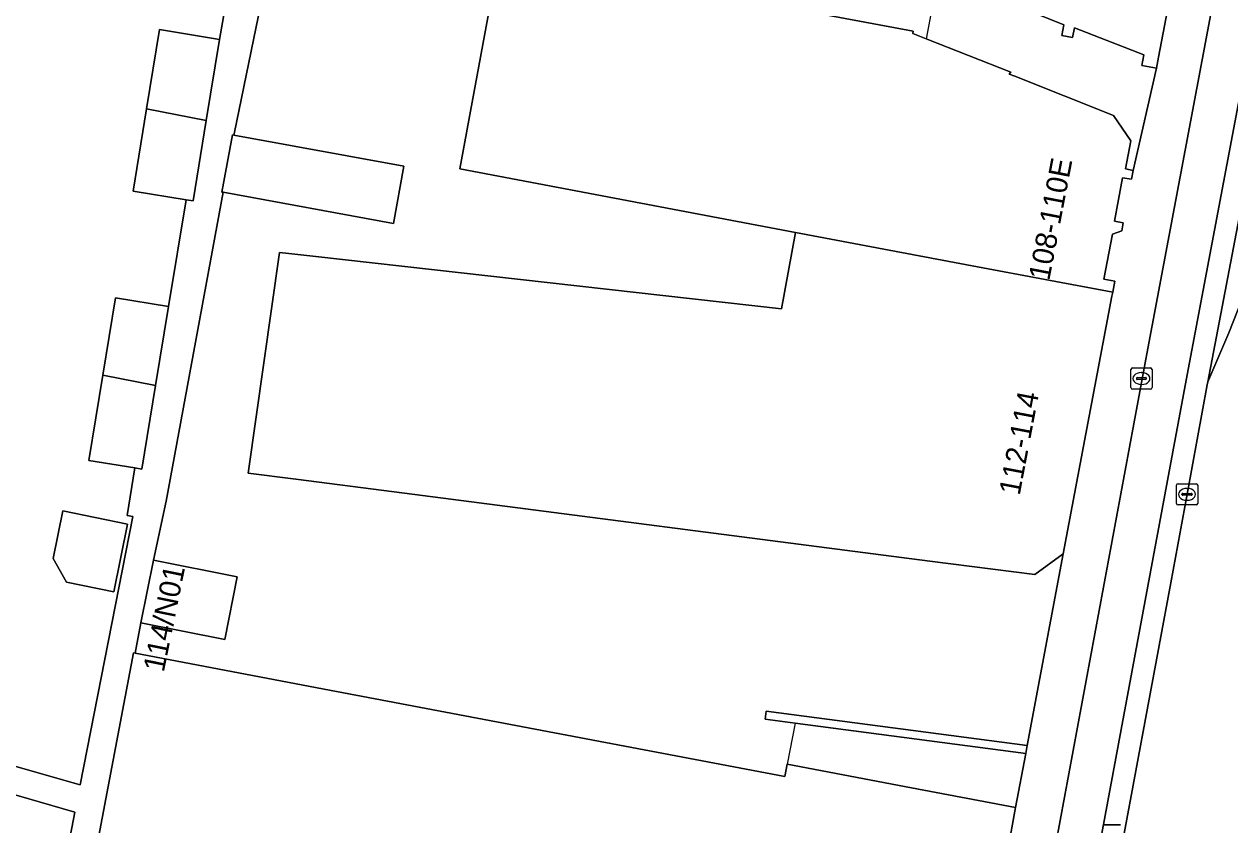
# Model space of a CAD drawing. Extents: x 161402 to 161933, y 381647 to 382315.
# Drawn here: x 161804.7 to 161861.6, y 381758.6 to 381796.3 of the extents above; entities that cross this region are included whole.
import ezdxf

# ---------------------------------------------------------------- set-up
doc = ezdxf.new("R2010")
doc.units = 0
for name, color, linetype in [('IMGEO_Berm_open', 7, 'Continuous'), ('IMGEO_Brandkraan', 7, 'Continuous'), ('IMGEO_Erf', 7, 'Continuous'), ('IMGEO_Fietspad_gesloten', 7, 'Continuous'), ('IMGEO_Kolk', 7, 'Continuous'), ('IMGEO_Pand', 7, 'Continuous'), ('IMGEO_Pand_nummerreeks', 7, 'Continuous'), ('IMGEO_Pand_overbouw', 7, 'Continuous'), ('IMGEO_Parkeervlak_open', 7, 'Continuous'), ('IMGEO_Rijbaan_lokaal_gesloten', 7, 'Continuous'), ('IMGEO_Voetpad_open', 7, 'Continuous'), ('IMGEO_Wegwijzer', 7, 'Continuous')]:
    doc.layers.add(name, color=color, linetype=linetype)

msp = doc.modelspace()

# ---------------------------------------------------------------- linework, layer by layer
at = {"layer": 'IMGEO_Berm_open'}
msp.add_lwpolyline([(161855.069, 381750), (161856.164, 381755.911), (161857.682, 381764.091), (161858.781, 381770.01), (161859.554, 381774.178), (161860.503, 381779.34), (161860.529, 381779.475), (161865.316, 381804.498), (161864.254, 381804.698), (161859.509, 381779.56), (161854.016, 381750), (161850.643, 381731.85), (161849.541, 381725.922), (161844.249, 381697.445)], dxfattribs=at)
at = {"layer": 'IMGEO_Brandkraan'}
for p, q in [((161856.902, 381779.209), (161856.902, 381780.061)), ((161856.977, 381780.135), (161857.829, 381780.135)), ((161857.903, 381780.061), (161857.903, 381779.209)), ((161857.161, 381779.629), (161857.161, 381779.641)), ((161857.599, 381779.592), (161857.201, 381779.592)), ((161857.204, 381779.678), (161857.602, 381779.678)), ((161857.39, 381779.915), (161857.415, 381779.915)), ((161857.645, 381779.641), (161857.645, 381779.629)), ((161857.829, 381779.135), (161856.977, 381779.135)), ((161857.413, 381779.355), (161857.388, 381779.355))]:
    msp.add_line(p, q, dxfattribs=at)
for points in [[(161856.902, 381779.209), (161856.902, 381780.061)], [(161856.977, 381780.135), (161857.829, 381780.135)], [(161857.903, 381780.061), (161857.903, 381779.209)], [(161857.829, 381779.135), (161856.977, 381779.135)]]:
    msp.add_lwpolyline(points, dxfattribs=at)
for centre, radius, start, end in [((161856.979, 381780.059), 0.0765, 91.552, 178.448), ((161856.979, 381780.059), 0.0765, 91.552, 178.448), ((161857.827, 381780.059), 0.0765, 1.552, 88.448), ((161857.827, 381780.059), 0.0765, 1.552, 88.448), ((161857.201, 381779.638), 0.0403, 85.8775, 175.7526), ((161857.198, 381779.628), 0.0366, 178.938, 274.7102), ((161857.602, 381779.635), 0.043, 264.8664, 352.4533), ((161857.606, 381779.64), 0.0386, 1.7309, 96.639), ((161856.979, 381779.211), 0.0765, 181.552, 268.448), ((161856.979, 381779.211), 0.0765, 181.552, 268.448), ((161857.827, 381779.211), 0.0765, 271.552, 358.448), ((161857.827, 381779.211), 0.0765, 271.552, 358.448)]:
    msp.add_arc(centre, radius, start, end, dxfattribs=at)
for centre, major_axis, ratio, start_param, end_param in [((161857.389, 381779.635), (-0.387, 0.002), 0.722429, 4.712389, 7.853982), ((161857.414, 381779.635), (-0.39, 0.002), 0.717154, 1.570796, 4.712389)]:
    msp.add_ellipse(centre, major_axis=major_axis, ratio=ratio, start_param=start_param, end_param=end_param, dxfattribs=at)
at = {"layer": 'IMGEO_Erf'}
for points in [[(161820.446, 381819.524), (161814.613, 381791.164), (161814.602, 381791.103), (161822.621, 381789.643), (161822.13, 381786.95), (161814.104, 381788.412), (161811.409, 381773.853), (161810.816, 381771.077), (161814.765, 381770.281), (161814.17, 381767.332), (161810.222, 381768.128), (161809.949, 381766.688), (161819.44, 381764.889), (161840.589, 381760.879), (161840.698, 381761.458), (161846.555, 381760.347), (161851.467, 381759.416), (161851.943, 381761.958), (161841.065, 381763.395), (161839.66, 381763.58), (161839.71, 381763.956), (161852.013, 381762.331), (161853.707, 381771.374), (161852.381, 381770.396), (161847.423, 381771.033), (161822.163, 381774.29), (161817.528, 381774.888), (161815.284, 381775.177), (161816.76, 381785.582), (161817.2, 381785.532), (161818.468, 381785.39), (161840.426, 381782.925), (161841.091, 381786.52), (161825.253, 381789.517), (161827.976, 381804.229)], [(161794.436, 381764.163), (161807.363, 381760.485), (161809.842, 381773.13), (161809.566, 381773.183), (161809.933, 381775.423), (161807.766, 381775.778), (161808.424, 381779.8), (161809.02, 381783.443), (161811.524, 381783.033), (161812.348, 381788.06), (161809.85, 381788.469), (161810.485, 381792.348), (161811.097, 381796.082), (161813.929, 381795.618), (161814.791, 381800.53)], [(161840.218, 381797.195), (161846.644, 381796.006), (161846.624, 381795.895), (161847.248, 381795.649), (161851.239, 381794.077), (161851.163, 381793.987), (161851.433, 381793.88), (161856.08, 381792.037), (161856.9, 381790.844), (161856.653, 381789.512), (161857.009, 381789.446), (161858.115, 381794.262), (161857.427, 381794.392), (161857.521, 381794.895), (161854.239, 381796.167), (161854.154, 381795.713), (161853.653, 381795.807), (161853.746, 381796.3), (161850.716, 381797.533)], [(161804.575, 381746.036), (161807.111, 381759.198), (161793.961, 381762.994)]]:
    msp.add_lwpolyline(points, dxfattribs=at)
msp.add_lwpolyline([(161809.588, 381772.777), (161808.944, 381769.581), (161806.712, 381770.031), (161806.084, 381771.151), (161806.536, 381773.392)], close=True, dxfattribs=at)
at = {"layer": 'IMGEO_Fietspad_gesloten'}
for points in [[(161910.061, 382061.001), (161905.702, 382037.375), (161898.752, 382000), (161887.89, 381941.593), (161886.669, 381935.154), (161880.56, 381902.497), (161879.486, 381896.758), (161857.65, 381780.798), (161851.928, 381750), (161842.232, 381697.819)], [(161844.249, 381697.445), (161849.541, 381725.922), (161850.643, 381731.85), (161854.016, 381750), (161859.509, 381779.56), (161864.254, 381804.698), (161864.714, 381807.133), (161867.323, 381820.954), (161867.824, 381823.608), (161869.899, 381834.602), (161881.54, 381896.271)]]:
    msp.add_lwpolyline(points, dxfattribs=at)
at = {"layer": 'IMGEO_Kolk'}
for p, q in [((161859.052, 381773.752), (161859.052, 381774.604)), ((161859.127, 381774.678), (161859.979, 381774.678)), ((161859.54, 381774.458), (161859.565, 381774.458)), ((161860.053, 381774.604), (161860.053, 381773.752)), ((161859.311, 381774.172), (161859.311, 381774.184)), ((161859.749, 381774.135), (161859.351, 381774.135)), ((161859.354, 381774.221), (161859.752, 381774.221)), ((161859.563, 381773.898), (161859.538, 381773.898)), ((161859.795, 381774.184), (161859.795, 381774.172)), ((161859.979, 381773.678), (161859.127, 381773.678))]:
    msp.add_line(p, q, dxfattribs=at)
for points in [[(161859.052, 381773.752), (161859.052, 381774.604)], [(161859.127, 381774.678), (161859.979, 381774.678)], [(161860.053, 381774.604), (161860.053, 381773.752)], [(161859.979, 381773.678), (161859.127, 381773.678)]]:
    msp.add_lwpolyline(points, dxfattribs=at)
for centre, radius, start, end in [((161859.129, 381774.602), 0.0765, 91.552, 178.448), ((161859.129, 381774.602), 0.0765, 91.552, 178.448), ((161859.977, 381774.602), 0.0765, 1.552, 88.448), ((161859.977, 381774.602), 0.0765, 1.552, 88.448), ((161859.129, 381773.754), 0.0765, 181.552, 268.448), ((161859.129, 381773.754), 0.0765, 181.552, 268.448), ((161859.351, 381774.181), 0.0403, 85.8775, 175.7526), ((161859.348, 381774.171), 0.0366, 178.938, 274.7102), ((161859.752, 381774.178), 0.043, 264.8664, 352.4533), ((161859.756, 381774.183), 0.0386, 1.7309, 96.639), ((161859.977, 381773.754), 0.0765, 271.552, 358.448), ((161859.977, 381773.754), 0.0765, 271.552, 358.448)]:
    msp.add_arc(centre, radius, start, end, dxfattribs=at)
for centre, major_axis, ratio, start_param, end_param in [((161859.539, 381774.178), (-0.387, 0.002), 0.722429, 4.712389, 7.853982), ((161859.564, 381774.178), (-0.39, 0.002), 0.717154, 1.570796, 4.712389)]:
    msp.add_ellipse(centre, major_axis=major_axis, ratio=ratio, start_param=start_param, end_param=end_param, dxfattribs=at)
at = {"layer": 'IMGEO_Pand'}
for points in [[(161850.716, 381797.533), (161853.746, 381796.3), (161853.653, 381795.807), (161854.154, 381795.713), (161854.239, 381796.167), (161857.521, 381794.895), (161857.427, 381794.392), (161858.115, 381794.262), (161858.21, 381794.775), (161860.511, 381806.869)], [(161827.976, 381804.229), (161825.253, 381789.517), (161841.091, 381786.52), (161849.676, 381784.895), (161856.045, 381783.706), (161856.14, 381784.219), (161855.635, 381784.312), (161856.03, 381786.443), (161856.477, 381786.601), (161856.545, 381786.97), (161856.131, 381787.047), (161856.511, 381789.101), (161856.93, 381789.024), (161857.009, 381789.446), (161856.653, 381789.512), (161856.9, 381790.844), (161856.08, 381792.037), (161851.433, 381793.88), (161851.163, 381793.987), (161851.239, 381794.077), (161847.248, 381795.649), (161846.624, 381795.895), (161846.644, 381796.006), (161840.218, 381797.195)], [(161851.119, 381757.504), (161851.467, 381759.416), (161846.555, 381760.347), (161840.698, 381761.458), (161840.589, 381760.879), (161819.44, 381764.889), (161809.949, 381766.688), (161809.872, 381766.703), (161807.718, 381755.345)]]:
    msp.add_lwpolyline(points, dxfattribs=at)
for points in [[(161813.302, 381791.79), (161813.929, 381795.618), (161811.097, 381796.082), (161810.485, 381792.348)], [(161813.302, 381791.79), (161810.485, 381792.348), (161809.85, 381788.469), (161812.348, 381788.06), (161812.682, 381788.005)], [(161822.621, 381789.643), (161814.602, 381791.103), (161814.532, 381791.116), (161814.041, 381788.423), (161814.104, 381788.412), (161822.13, 381786.95)], [(161856.009, 381783.513), (161856.045, 381783.706), (161849.676, 381784.895), (161841.091, 381786.52), (161840.426, 381782.925), (161818.468, 381785.39), (161817.2, 381785.532), (161816.76, 381785.582), (161815.284, 381775.177), (161817.528, 381774.888), (161822.163, 381774.29), (161847.423, 381771.033), (161852.381, 381770.396), (161853.707, 381771.374)], [(161810.915, 381779.306), (161811.524, 381783.033), (161809.02, 381783.443), (161808.424, 381779.8)], [(161810.915, 381779.306), (161808.424, 381779.8), (161807.766, 381775.778), (161809.933, 381775.423), (161810.27, 381775.368)], [(161806.084, 381771.151), (161806.712, 381770.031), (161808.944, 381769.581), (161809.588, 381772.777), (161806.536, 381773.392)], [(161814.17, 381767.332), (161814.765, 381770.281), (161810.816, 381771.077), (161810.222, 381768.128)], [(161839.71, 381763.956), (161839.66, 381763.58), (161841.065, 381763.395), (161851.943, 381761.958), (161852.013, 381762.331)]]:
    msp.add_lwpolyline(points, close=True, dxfattribs=at)
at = {"layer": 'IMGEO_Pand_overbouw'}
for points in [[(161857.009, 381789.446), (161858.115, 381794.262), (161857.427, 381794.392), (161857.521, 381794.895), (161854.239, 381796.167), (161854.154, 381795.713), (161853.653, 381795.807), (161853.746, 381796.3), (161850.716, 381797.533), (161850.627, 381797.062), (161850.117, 381797.158), (161850.239, 381797.804), (161849.663, 381797.923), (161849.682, 381798.222), (161847.86, 381798.902), (161847.248, 381795.649), (161851.239, 381794.077), (161851.163, 381793.987), (161851.433, 381793.88), (161856.08, 381792.037), (161856.9, 381790.844), (161856.653, 381789.512)], [(161851.943, 381761.958), (161841.065, 381763.395), (161840.698, 381761.458), (161846.555, 381760.347), (161851.467, 381759.416)]]:
    msp.add_lwpolyline(points, close=True, dxfattribs=at)
at = {"layer": 'IMGEO_Parkeervlak_open'}
msp.add_lwpolyline([(161865.316, 381804.498), (161860.529, 381779.475), (161861.521, 381781.789), (161862.376, 381783.945), (161863.081, 381785.029), (161863.613, 381786.178), (161864.093, 381787.863), (161884.15, 381893.504)], dxfattribs=at)
at = {"layer": 'IMGEO_Rijbaan_lokaal_gesloten'}
msp.add_lwpolyline([(161884.17, 381893.607), (161884.15, 381893.504), (161864.093, 381787.863), (161863.613, 381786.178), (161863.081, 381785.029), (161862.376, 381783.945), (161861.521, 381781.789), (161860.529, 381779.475), (161860.503, 381779.34), (161859.554, 381774.178), (161858.781, 381770.01), (161857.682, 381764.091), (161856.164, 381755.911), (161855.069, 381750), (161851.669, 381731.66), (161850.569, 381725.731), (161845.879, 381700.449), (161845.656, 381699.227), (161845.077, 381696.29), (161841.891, 381681.821), (161841.621, 381680.659), (161841.162, 381678.679), (161840.43, 381675.643), (161840.392, 381675.483)], dxfattribs=at)
at = {"layer": 'IMGEO_Voetpad_open'}
for points in [[(161842.232, 381697.819), (161851.928, 381750), (161857.65, 381780.798), (161879.486, 381896.758)], [(161801.301, 381721.11), (161806.126, 381746.844), (161806.71, 381750), (161806.895, 381751.005), (161806.917, 381751.12), (161807.718, 381755.345), (161809.872, 381766.703), (161809.949, 381766.688), (161810.222, 381768.128), (161810.816, 381771.077), (161811.409, 381773.853), (161814.104, 381788.412), (161814.041, 381788.423), (161814.532, 381791.116), (161814.602, 381791.103), (161814.613, 381791.164), (161820.446, 381819.524)], [(161860.511, 381806.869), (161858.21, 381794.775), (161858.115, 381794.262), (161857.009, 381789.446), (161856.93, 381789.024), (161856.511, 381789.101), (161856.131, 381787.047), (161856.545, 381786.97), (161856.477, 381786.601), (161856.03, 381786.443), (161855.635, 381784.312), (161856.14, 381784.219), (161856.045, 381783.706), (161856.009, 381783.513), (161853.707, 381771.374), (161852.013, 381762.331), (161851.943, 381761.958), (161851.467, 381759.416), (161851.119, 381757.504)], [(161814.791, 381800.53), (161813.929, 381795.618), (161813.302, 381791.79), (161812.682, 381788.005), (161812.348, 381788.06), (161811.524, 381783.033), (161810.915, 381779.306), (161810.27, 381775.368), (161809.933, 381775.423), (161809.566, 381773.183), (161809.842, 381773.13), (161807.363, 381760.485), (161794.436, 381764.163)], [(161793.961, 381762.994), (161807.111, 381759.198), (161804.575, 381746.036)]]:
    msp.add_lwpolyline(points, dxfattribs=at)
at = {"layer": 'IMGEO_Wegwijzer'}
for p, q in [((161855.623, 381758.598), (161856.413, 381758.598)), ((161856.413, 381758.598), (161855.623, 381758.598))]:
    msp.add_line(p, q, dxfattribs=at)

# ---------------------------------------------------------------- texts
at = {"layer": 'IMGEO_Pand_nummerreeks'}
for s, rotation, p in [('108-110E', 79.114, (161853.053, 381784.218)), ('112-114', 79.263, (161851.657, 381774.094)), ('114/N01', 78.5134, (161811.298, 381765.758))]:
    msp.add_text(s, height=1, rotation=rotation, dxfattribs=at).set_placement(p)

doc.saveas('drawing.dxf')
